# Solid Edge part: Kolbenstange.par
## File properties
Username: bmolnar
Dokumentum tartalom típus: 0
Author: bmolnar
Last saved by: bmolnar
Revision: 87
Sűrűség: 0,000 kg/m^3
Pontosság: 0,990
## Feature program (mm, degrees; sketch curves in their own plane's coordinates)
base feature "unnamed BaseFeature 1"
thread "unnamed Thread 1"
sketch for "unnamed Protrusion 1" plane through (0, 0, -18.3) normal (0, 0, -1) x-axis (0, -1, 0)
  circle centre (0, 0) radius 10
extrude "unnamed Protrusion 1" add finite 6.7 along +normal
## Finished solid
Body 1: solid body, 17 faces, 23 edges, 8 vertices.
  Faces by surface: plane 8, cylinder 4, torus 3, cone 2
  Edges by curve: circle 13, line 6, ellipse 2, intersection 2
Bounding box of the edges (mm; curved faces can reach further): 20.000 x 20.000 x 121.000, from (-10, -10, -25) to (10, 10, 96).
Cylindrical faces by radius (mm): R2.9 x1, R4 x1, R5 x1, R10 x1
Conical faces (half-angle, radius in mm at the cone's reference point): 20 deg R3.5 x1, 60 deg R3.55 x1
Toroidal faces (ring radius, tube radius in mm): R3.3 r0.4 x2, R3.8 r1.2 x1
Planar faces by outward normal: +x 1, +z 3, -x 1, -z 1, oblique 2
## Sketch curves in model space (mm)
circle centre (0, 0, -18.3) radius 10
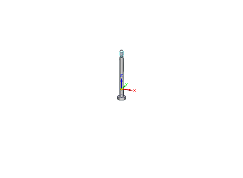
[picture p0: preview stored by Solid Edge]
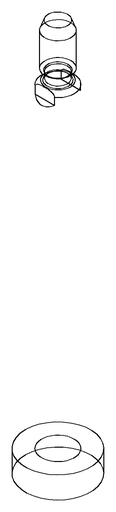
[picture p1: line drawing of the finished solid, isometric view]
